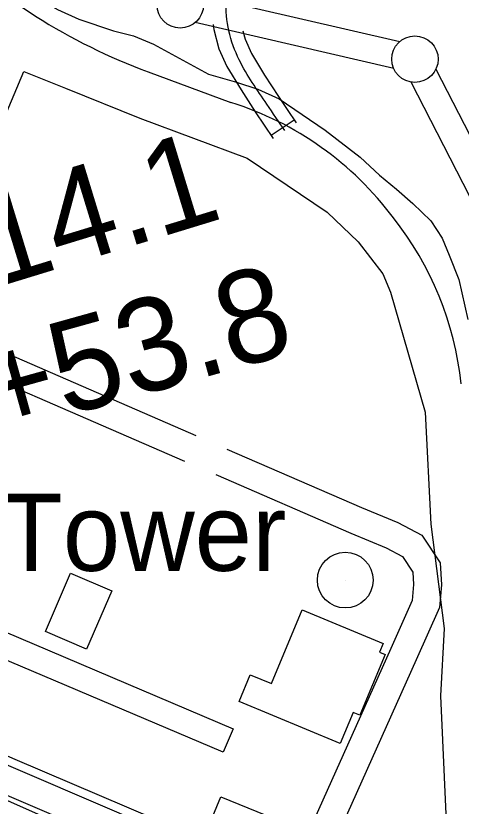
# Model space of a CAD drawing. Extents: x 3651524 to 3689615, y 505651 to 531377.
# Drawn here: x 3656595 to 3657075, y 528211 to 529062 of the extents above; entities that cross this region are included whole.
import ezdxf

# ---------------------------------------------------------------- set-up
doc = ezdxf.new("R2010")
doc.units = 0
for name, color, linetype in [('V-BLDG-OTLN', 7, 'Continuous'), ('V-DOMW-IDEN', 7, 'Continuous'), ('V-DOMW-TANK', 7, 'Continuous'), ('V-LEVE-TOET', 7, 'Continuous'), ('V-RAIL-TRAK', 7, 'Continuous'), ('V-ROAD-CNTR', 7, 'Continuous'), ('V-SITE-OTLN', 7, 'Continuous'), ('V-SURV-IDEN', 7, 'Continuous'), ('V-SURV-LINE', 7, 'Continuous')]:
    doc.layers.add(name, color=color, linetype=linetype)

msp = doc.modelspace()

# ---------------------------------------------------------------- linework, layer by layer
at = {"layer": 'V-BLDG-OTLN'}
for points in [[(3656698.849, 528442.693), (3656671.745, 528379.928), (3656627.294, 528399.121), (3656654.397, 528461.886)], [(3656818.65, 528269.147), (3656505.462, 528402.001), (3656516.14, 528427.177), (3656829.331, 528294.323)], [(3656903.786, 528422.26), (3656990.934, 528386.033), (3656987.027, 528376.632), (3656992.989, 528374.154), (3656965.795, 528308.741), (3656958.539, 528311.758), (3656944.627, 528278.291), (3656835.78, 528323.54), (3656847.789, 528352.427), (3656870.791, 528342.885)], [(3656815.988, 528220.929), (3656903.149, 528185.488), (3656888, 528148.231), (3656800.839, 528183.67)]]:
    msp.add_lwpolyline(points, close=True, dxfattribs=at)
at = {"layer": 'V-DOMW-TANK'}
msp.add_line((3656950.064, 528454.317), (3656950.064, 528454.317), dxfattribs=at)
msp.add_circle((3656950.064, 528454.316), 30, dxfattribs=at)
at = {"layer": 'V-LEVE-TOET'}
for points in [[(3656606.805, 529098.986), (3656623.37, 529078.429), (3656640.253, 529068.77), (3656663.24, 529058.379), (3656700.462, 529045.82), (3656722.134, 529040.192), (3656743.776, 529031.171)], [(3656743.776, 529031.171), (3656802.701, 528998.976), (3656832.851, 528990.287), (3656855.897, 528982.873), (3656878.907, 528972.496), (3656928.317, 528938.64), (3656965.922, 528909.684), (3656987.039, 528890.428), (3657005.242, 528875.363), (3657022.842, 528859.712), (3657042.186, 528841.074), (3657054.41, 528822.525), (3657061.889, 528804.038), (3657072.236, 528777.799), (3657081.78, 528734.957)]]:
    msp.add_lwpolyline(points, dxfattribs=at)
at = {"layer": 'V-RAIL-TRAK'}
msp.add_lwpolyline([(3656746.94, 528196.185), (3656594.841, 528261.248), (3656427.069, 528334.669), (3655850.153, 528582.276), (3655828.991, 528589.317), (3655820.445, 528591.875), (3655811.839, 528594.222), (3655803.178, 528596.358), (3655794.468, 528598.281), (3655785.713, 528599.989), (3655776.919, 528601.482), (3655768.09, 528602.76), (3655759.232, 528603.819)], dxfattribs=at)
at = {"layer": 'V-ROAD-CNTR'}
msp.add_line((3656895.22, 528949.633), (3656870.372, 528932.823), dxfattribs=at)
for points in [[(3656807.936, 529052.342), (3656808.568, 529047.009), (3656813.913, 529026.425), (3656822.723, 529007.227), (3656837.864, 528982.162), (3656853.163, 528958.527), (3656862.761, 528944.074), (3656872.431, 528929.78)], [(3656839.914, 529045.659), (3656842.285, 529036.529), (3656849.281, 529021.283), (3656863.302, 528998.072), (3656878.251, 528974.977), (3656887.681, 528960.778), (3656897.279, 528946.59)], [(3656738.046, 529001.594), (3656827.068, 528968.485)], [(3656810.634, 528567.869), (3656955.96, 528504.765), (3656993.926, 528489.219), (3657011.537, 528479.706), (3657022.63, 528462.99), (3657023.486, 528449.411), (3657022.016, 528432.316), (3656998.959, 528380.636), (3656888.65, 528134.243), (3656885.261, 528127.651), (3656876.311, 528129.515), (3656737.572, 528190.066), (3656178.242, 528430.084), (3655866.967, 528560.024), (3655858.644, 528565), (3655856.407, 528568.958), (3655859.596, 528583.183), (3655974.933, 528836.399), (3656017.727, 528928.859), (3656018.292, 528929.103), (3656022.754, 528928.339), (3656058.225, 528909.513)], [(3656058.853, 528909.198), (3656451.375, 528723.869), (3656777.201, 528582.387)], [(3656416.55, 528773.487), (3656463.757, 528751.198), (3656789.149, 528609.905)], [(3656822.582, 528595.387), (3656967.62, 528532.409), (3657006.776, 528516.375), (3657032.389, 528502.54), (3657052.064, 528472.89), (3657053.568, 528449.069), (3657051.472, 528424.708), (3657026.349, 528368.396), (3656935.547, 528165.577)], [(3656874.692, 528097.49), (3656725.657, 528162.534), (3656166.548, 528402.456), (3655846.791, 528535.938)]]:
    msp.add_lwpolyline(points, dxfattribs=at)
for centre, radius, start, end in [((3656948.624, 529580.375), 615.898, 224.802047, 250.007167), ((3656722.753, 528636.659), 347.837, 36.648994, 72.548555), ((3656729.898, 528628.984), 346.842, 6.074049, 38.370979)]:
    msp.add_arc(centre, radius, start, end, dxfattribs=at)
msp.add_spline([(3656884.855, 528938.185), (3656865.707, 528966.752), (3656836.002, 529014.255), (3656822.001, 529078.27), (3656843.959, 529138.257), (3656895.564, 529201.721)], degree=3, dxfattribs=at)
at = {"layer": 'V-SITE-OTLN'}
msp.add_lwpolyline([(3655790.35, 528156.345), (3655782.791, 528212.923), (3655895.611, 528486.378), (3655876.872, 528497.313), (3656050.552, 528953.2), (3656489.975, 528744.687), (3656503.527, 528755.328), (3656559.273, 528896.064), (3656604.047, 529001.881), (3656648.843, 528983.78), (3656728.919, 528951.686), (3656844.392, 528908.389), (3656930.475, 528850.47), (3656964.007, 528818.474), (3656990.404, 528784.199), (3656998.838, 528764.36), (3657035.872, 528635.239), (3657042.231, 528514.401), (3657056.591, 528402.144), (3657052.512, 528329.584), (3657058.69, 528194.541)], dxfattribs=at)
msp.add_lwpolyline([(3655991.498, 528442.338), (3656084.107, 528405.718), (3656094.019, 528426.628), (3656358.596, 528314.172), (3656556.547, 528230.317), (3656745.162, 528146.163), (3656677.666, 527993.558), (3656639.147, 527906.022), (3656505.495, 527961.681), (3656510.248, 527971.36), (3656389.404, 528024.569), (3656324.659, 527960.604), (3656165.033, 528025.443), (3656083.326, 528063.518), (3656089.667, 528076.682), (3656022.642, 528104.123), (3656010.248, 528066.905), (3655860.35, 528132.433), (3655930.226, 528290.069)], close=True, dxfattribs=at)
at = {"layer": 'V-SURV-LINE'}
for points in [[(3656795.313, 529083.737), (3657008.902, 529034.272)], [(3657002.152, 529005.041), (3656788.563, 529054.506)], [(3657047.48, 529004.239), (3657138.831, 528826.653)], [(3657112.158, 528812.921), (3657020.807, 528990.507)]]:
    msp.add_lwpolyline(points, dxfattribs=at)
for centre in [(3656772.465, 529073.631), (3657025, 529015.147)]:
    msp.add_circle(centre, 25, dxfattribs=at)

# ---------------------------------------------------------------- texts
at = {"layer": 'V-DOMW-IDEN'}
msp.add_text('Water Tower', height=82.99983, dxfattribs=at).set_placement((3656251.457, 528464.273))
at = {"layer": 'V-SURV-IDEN'}
for s, rotation, p in [('561+14.1', 17.028536, (3656283.677, 528680.161)), ('563+53.8', 15.607613, (3656357.972, 528549.431))]:
    msp.add_text(s, height=100, rotation=rotation, dxfattribs=at).set_placement(p)

doc.saveas('drawing.dxf')
